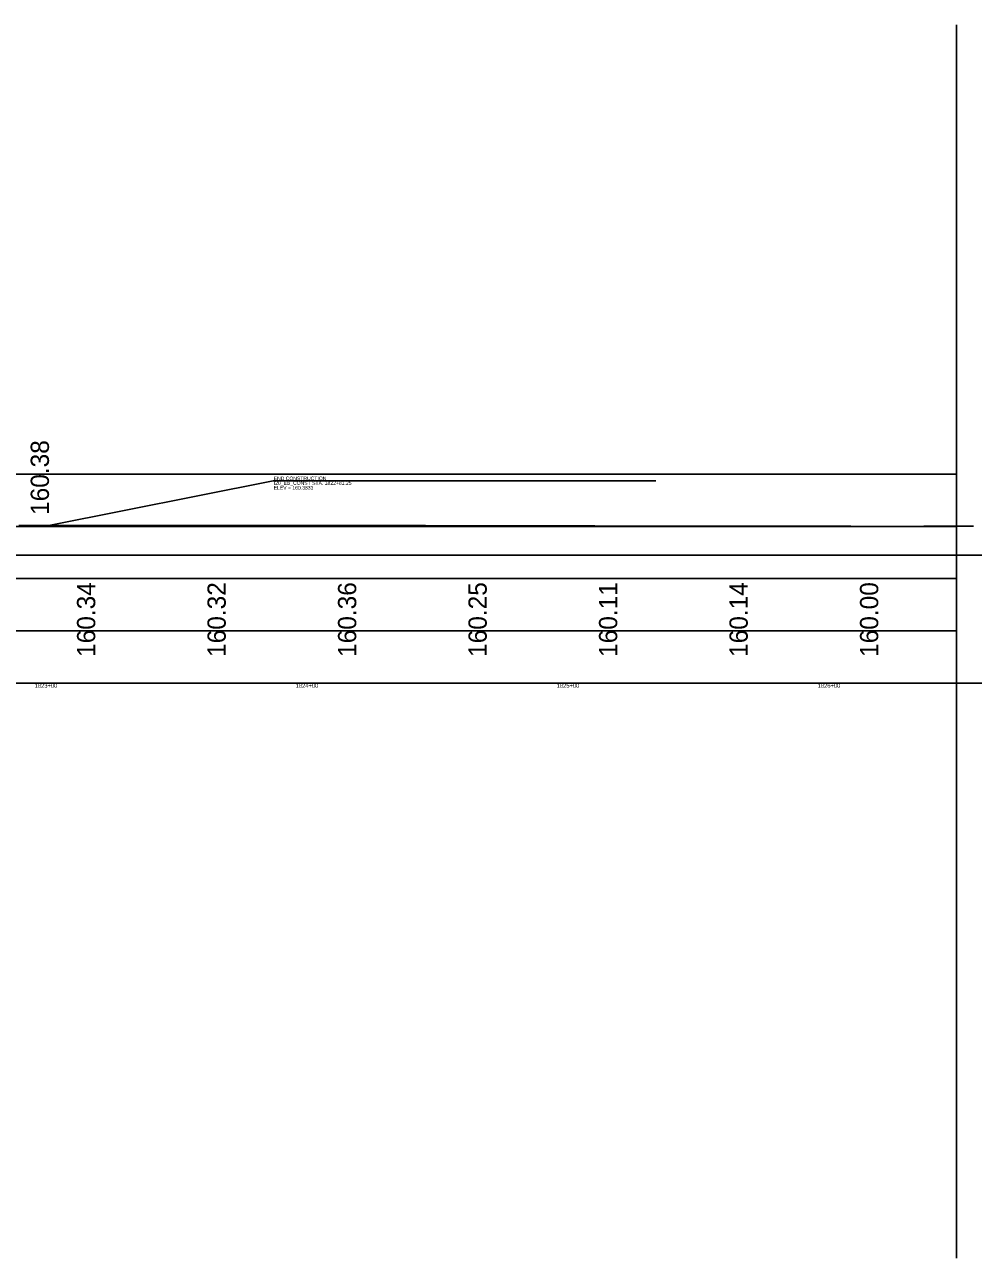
# Model space of a CAD drawing. Extents: x 2126510 to 2136144, y 865066 to 868066.
# Drawn here: x 2134895 to 2135258.4, y 867594 to 868066.5 of the extents above; entities that cross this region are included whole.
import ezdxf

# ---------------------------------------------------------------- set-up
doc = ezdxf.new("R2010")
doc.units = 0
doc.layers.add('RD_EX_GuardRail', color=7, linetype='Continuous')
doc.layers.add('RD_EX_Misc', color=7, linetype='Continuous')

msp = doc.modelspace()

# ---------------------------------------------------------------- linework, layer by layer
at = {"layer": 'RD_EX_GuardRail'}
for p, q in [((2135251.98, 868066.49), (2135251.98, 867593.96)), ((2135251.98, 867894.32), (2130671.73, 867894.32)), ((2135251.98, 867874.32), (2133154.4, 867874.32)), ((2135251.98, 867854.32), (2130671.73, 867854.32)), ((2135251.98, 867834.32), (2130671.73, 867834.32)), ((2135251.98, 867814.32), (2130671.73, 867814.32))]:
    msp.add_line(p, q, dxfattribs=at)
at = {"layer": 'RD_EX_Misc'}
for p, q in [((2135136.81, 867891.82), (2134990.2, 867891.82)), ((2134892.76, 867874.72), (2134904.26, 867874.7)), ((2131523, 867814.32), (2135677.25, 867814.32))]:
    msp.add_line(p, q, dxfattribs=at)
for points in [[(2134990.2, 867891.82), (2134904.24, 867874.7)], [(2134894.47, 867874.71), (2134895.47, 867874.71), (2134896.47, 867874.71), (2134897.47, 867874.71), (2134898.47, 867874.71), (2134899.47, 867874.71), (2134900.47, 867874.71), (2134901.47, 867874.71), (2134902.47, 867874.7), (2134903.47, 867874.7), (2134904.47, 867874.7), (2134905.47, 867874.7), (2134906.47, 867874.69), (2134907.47, 867874.69), (2134908.47, 867874.69), (2134909.47, 867874.68), (2134910.47, 867874.68), (2134911.47, 867874.68), (2134912.47, 867874.68), (2134913.47, 867874.67), (2134914.47, 867874.67), (2134915.47, 867874.67), (2134916.47, 867874.67), (2134917.47, 867874.66), (2134918.47, 867874.66), (2134919.47, 867874.66), (2134920.47, 867874.66), (2134921.47, 867874.65), (2134922.47, 867874.65), (2134923.47, 867874.65), (2134924.47, 867874.65), (2134925.47, 867874.64), (2134926.47, 867874.64), (2134927.47, 867874.64), (2134928.47, 867874.64), (2134929.47, 867874.63), (2134930.47, 867874.63), (2134931.47, 867874.63), (2134932.47, 867874.63), (2134933.47, 867874.62), (2134934.47, 867874.62), (2134935.47, 867874.62), (2134936.47, 867874.62), (2134937.47, 867874.61), (2134938.47, 867874.61), (2134939.47, 867874.61), (2134940.47, 867874.61), (2134941.47, 867874.61), (2134942.47, 867874.61), (2134943.47, 867874.61), (2134944.47, 867874.61), (2134945.47, 867874.61), (2134946.47, 867874.61), (2134947.47, 867874.61), (2134948.47, 867874.61), (2134949.47, 867874.61), (2134950.47, 867874.61), (2134951.47, 867874.61), (2134952.47, 867874.61), (2134953.47, 867874.61), (2134954.47, 867874.61), (2134955.47, 867874.61), (2134956.47, 867874.61), (2134957.47, 867874.61), (2134958.47, 867874.61), (2134959.47, 867874.61), (2134960.47, 867874.62), (2134961.47, 867874.62), (2134962.47, 867874.62), (2134963.47, 867874.62), (2134964.47, 867874.62), (2134965.47, 867874.62), (2134966.47, 867874.62), (2134967.47, 867874.63), (2134968.47, 867874.63), (2134969.47, 867874.63), (2134970.47, 867874.63), (2134971.47, 867874.63), (2134972.47, 867874.63), (2134973.47, 867874.64), (2134974.47, 867874.64), (2134975.47, 867874.64), (2134976.47, 867874.64), (2134977.47, 867874.64), (2134978.47, 867874.65), (2134979.47, 867874.65), (2134980.47, 867874.65), (2134981.47, 867874.65), (2134982.47, 867874.65), (2134983.47, 867874.65), (2134984.47, 867874.65), (2134985.47, 867874.65), (2134986.47, 867874.66)], [(2134986.47, 867874.66), (2134987.47, 867874.66), (2134988.47, 867874.66), (2134989.47, 867874.66), (2134990.47, 867874.66), (2134991.47, 867874.66), (2134992.47, 867874.66), (2134993.47, 867874.66), (2134994.47, 867874.66), (2134995.47, 867874.66), (2134996.47, 867874.67), (2134997.47, 867874.67), (2134998.47, 867874.67), (2134999.47, 867874.67), (2135000.47, 867874.67), (2135001.47, 867874.67), (2135002.47, 867874.67), (2135003.47, 867874.67), (2135004.47, 867874.67), (2135005.47, 867874.67), (2135006.47, 867874.67), (2135007.47, 867874.68), (2135008.47, 867874.68), (2135009.47, 867874.68), (2135010.47, 867874.68), (2135011.47, 867874.68), (2135012.47, 867874.68), (2135013.47, 867874.68), (2135014.47, 867874.68), (2135015.47, 867874.68), (2135016.47, 867874.68), (2135017.47, 867874.68), (2135018.47, 867874.69), (2135019.47, 867874.69), (2135020.47, 867874.69), (2135021.47, 867874.68), (2135022.47, 867874.68), (2135023.47, 867874.68), (2135024.47, 867874.67), (2135025.47, 867874.67), (2135026.47, 867874.67), (2135027.47, 867874.66), (2135028.47, 867874.66), (2135029.47, 867874.66), (2135030.47, 867874.65), (2135031.47, 867874.65), (2135032.47, 867874.64), (2135033.47, 867874.64), (2135034.47, 867874.64), (2135035.47, 867874.63), (2135036.47, 867874.63), (2135037.47, 867874.63), (2135038.47, 867874.62), (2135039.47, 867874.62), (2135040.47, 867874.62), (2135041.47, 867874.61), (2135042.47, 867874.61), (2135043.47, 867874.6), (2135044.47, 867874.6), (2135045.47, 867874.6), (2135046.47, 867874.6), (2135047.47, 867874.6), (2135048.47, 867874.6), (2135049.47, 867874.59), (2135050.47, 867874.59), (2135051.47, 867874.59), (2135052.47, 867874.59), (2135053.47, 867874.59), (2135054.47, 867874.59), (2135055.47, 867874.59), (2135056.47, 867874.58), (2135057.47, 867874.58), (2135058.47, 867874.58), (2135059.47, 867874.58), (2135060.47, 867874.58), (2135061.47, 867874.58), (2135062.47, 867874.57), (2135063.47, 867874.57), (2135064.47, 867874.57), (2135065.47, 867874.57), (2135066.47, 867874.57), (2135067.47, 867874.57), (2135068.47, 867874.57), (2135069.47, 867874.57), (2135070.47, 867874.56), (2135071.47, 867874.56), (2135072.47, 867874.56), (2135073.47, 867874.56), (2135074.47, 867874.56), (2135075.47, 867874.56), (2135076.47, 867874.56), (2135077.47, 867874.56), (2135078.47, 867874.56), (2135079.47, 867874.55), (2135080.47, 867874.55), (2135081.47, 867874.55), (2135082.47, 867874.55), (2135083.47, 867874.55), (2135084.47, 867874.55), (2135085.47, 867874.55), (2135086.47, 867874.55)], [(2135086.47, 867874.55), (2135087.47, 867874.55), (2135088.47, 867874.54), (2135089.47, 867874.54), (2135090.47, 867874.54), (2135091.47, 867874.54), (2135092.47, 867874.54), (2135093.47, 867874.54), (2135094.47, 867874.54), (2135095.47, 867874.54), (2135096.47, 867874.54), (2135097.47, 867874.53), (2135098.47, 867874.53), (2135099.47, 867874.53), (2135100.47, 867874.53), (2135101.47, 867874.52), (2135102.47, 867874.52), (2135103.47, 867874.51), (2135104.47, 867874.51), (2135105.47, 867874.5), (2135106.47, 867874.5), (2135107.47, 867874.5), (2135108.47, 867874.49), (2135109.47, 867874.49), (2135110.47, 867874.48), (2135111.47, 867874.48), (2135112.47, 867874.47), (2135113.47, 867874.47), (2135114.47, 867874.46), (2135115.47, 867874.46), (2135116.47, 867874.45), (2135117.47, 867874.45), (2135118.47, 867874.44), (2135119.47, 867874.44), (2135120.47, 867874.43), (2135121.47, 867874.43), (2135122.47, 867874.43), (2135123.47, 867874.43), (2135124.47, 867874.43), (2135125.47, 867874.43), (2135126.47, 867874.43), (2135127.47, 867874.43), (2135128.47, 867874.43), (2135129.47, 867874.43), (2135130.47, 867874.43), (2135131.47, 867874.43), (2135132.47, 867874.43), (2135133.47, 867874.43), (2135134.47, 867874.43), (2135135.47, 867874.43), (2135136.47, 867874.43), (2135137.47, 867874.43), (2135138.47, 867874.43), (2135139.47, 867874.43), (2135140.47, 867874.43), (2135141.47, 867874.43), (2135142.47, 867874.43), (2135143.47, 867874.43), (2135144.47, 867874.43), (2135145.47, 867874.43), (2135146.47, 867874.43), (2135147.47, 867874.43), (2135148.47, 867874.44), (2135149.47, 867874.44), (2135150.47, 867874.44), (2135151.47, 867874.44), (2135152.47, 867874.44), (2135153.47, 867874.44), (2135154.47, 867874.44), (2135155.47, 867874.44), (2135156.47, 867874.44), (2135157.47, 867874.44), (2135158.47, 867874.45), (2135159.47, 867874.45), (2135160.47, 867874.45), (2135161.47, 867874.45), (2135162.47, 867874.45), (2135163.47, 867874.45), (2135164.47, 867874.45), (2135165.47, 867874.45), (2135166.47, 867874.45), (2135167.47, 867874.45), (2135168.47, 867874.46), (2135169.47, 867874.46), (2135170.47, 867874.45), (2135171.47, 867874.46), (2135172.47, 867874.46), (2135173.47, 867874.46), (2135174.47, 867874.46), (2135175.47, 867874.46), (2135176.47, 867874.46), (2135177.47, 867874.46), (2135178.47, 867874.46), (2135179.47, 867874.46), (2135180.47, 867874.46), (2135181.47, 867874.45), (2135182.47, 867874.45), (2135183.47, 867874.44), (2135184.47, 867874.44), (2135185.47, 867874.43), (2135186.47, 867874.43)], [(2135186.47, 867874.43), (2135187.47, 867874.42), (2135188.47, 867874.42), (2135189.47, 867874.41), (2135190.47, 867874.41), (2135191.47, 867874.41), (2135192.47, 867874.4), (2135193.47, 867874.4), (2135194.47, 867874.39), (2135195.47, 867874.39), (2135196.47, 867874.38), (2135197.47, 867874.38), (2135198.47, 867874.37), (2135199.47, 867874.37), (2135200.47, 867874.36), (2135201.47, 867874.36), (2135202.47, 867874.36), (2135203.47, 867874.36), (2135204.47, 867874.35), (2135205.47, 867874.35), (2135206.47, 867874.35), (2135207.47, 867874.35), (2135208.47, 867874.34), (2135209.47, 867874.34), (2135210.47, 867874.34), (2135211.47, 867874.34), (2135212.47, 867874.33), (2135213.47, 867874.33), (2135214.47, 867874.33), (2135215.47, 867874.32), (2135216.47, 867874.32), (2135217.47, 867874.32), (2135218.47, 867874.31), (2135219.47, 867874.32), (2135220.47, 867874.32), (2135221.47, 867874.32), (2135222.47, 867874.32), (2135223.47, 867874.32), (2135224.47, 867874.32), (2135225.47, 867874.32), (2135226.47, 867874.32), (2135227.47, 867874.32), (2135228.47, 867874.32), (2135229.47, 867874.33), (2135230.47, 867874.33), (2135231.47, 867874.33), (2135232.47, 867874.33), (2135233.47, 867874.33), (2135234.47, 867874.33), (2135235.47, 867874.33), (2135236.47, 867874.33), (2135237.47, 867874.33), (2135238.47, 867874.33), (2135239.47, 867874.34), (2135240.47, 867874.34), (2135241.47, 867874.34), (2135242.47, 867874.34), (2135243.47, 867874.34), (2135244.47, 867874.34), (2135245.47, 867874.34), (2135246.47, 867874.34), (2135247.47, 867874.34), (2135248.47, 867874.34), (2135249.47, 867874.35), (2135250.47, 867874.35), (2135251.47, 867874.35), (2135252.47, 867874.35), (2135253.47, 867874.35), (2135254.47, 867874.35), (2135255.47, 867874.35), (2135256.47, 867874.35), (2135257.47, 867874.35), (2135258.47, 867874.35)], [(2131430.13, 867814.32), (2131430.13, 867863.32), (2136143.96, 867863.32)]]:
    msp.add_lwpolyline(points, dxfattribs=at)

# ---------------------------------------------------------------- texts
for s, p in [('160.38', (2134904.26, 867878.7)), ('160.34', (2134922, 867824.32)), ('160.32', (2134972, 867824.32)), ('160.36', (2135022, 867824.32)), ('160.25', (2135072, 867824.32)), ('160.11', (2135122, 867824.32)), ('160.14', (2135172, 867824.32)), ('160.00', (2135222, 867824.32))]:
    msp.add_text(s, height=7, rotation=90, dxfattribs=at).set_placement(p)
for s, height, p in [('END CONSTRUCTION', 1.4, (2134990.37, 867892.02)), ('ELEV = 160.3833', 1.4, (2134990.37, 867888.42)), ('I20_EB_CONST STA. 1822+81.25', 1.4, (2134990.37, 867890.22)), ('1823+00', 1.6, (2134898.79, 867812.52)), ('1824+00', 1.6, (2134998.79, 867812.52)), ('1825+00', 1.6, (2135098.79, 867812.52)), ('1826+00', 1.6, (2135198.79, 867812.52))]:
    msp.add_text(s, height=height, dxfattribs=at).set_placement(p)

doc.saveas('drawing.dxf')
